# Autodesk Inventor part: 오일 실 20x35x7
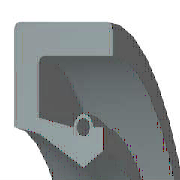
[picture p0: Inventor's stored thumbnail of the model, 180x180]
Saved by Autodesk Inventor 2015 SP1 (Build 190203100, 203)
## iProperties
IsCustomPart: 1
Created: 2012-02
Part Number: 오일 실 20x35x7
Material: 고무
Description: 회전 샤프트 립 유형 실 2 - 금속 케이스
Document SubType Name: Modeling
Standard: ISO 6194/1
Designer: mduedu
Standards Organization: ISO
Language: ko-KR
Size Designation: 20x35x7-유형 2
Categories: <MemberInstance><Categories><Category DisplayName="샤프트 부품" InternalName="7f7aeb1f-a693-4053-b835-cee3144e0d98" Mnemonic="SHFT"><Category DisplayName="실링" Intern
Density: 0.93 g/cm^3
Appearance: 고무 - 검은색 - 버전 1.1
Author: mduedu
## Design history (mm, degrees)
node "WorkPlane2"
node "WorkPoint1"
node "WorkPlane3"
body "Solid1"
node "스케치1"
revolve "회전1" stored, may be unused: angle "d37" = 360 deg
fillet "모깎기1" dims "d38" = 0.35 (= 0.05 x b)
sketch "스케치2"
  geometry: L1 (16, -0.35)-(16.8, -0.35); L2 (16, 0)-(16, -0.35); L3 (17.5, 0)-(16, 0); L4 (17.5, -7)-(17.5, 0); L5 (12.22, -7)-(17.5, -7); L6 (11.283, -4.2)-(12.22, -7); L7 (10.601, -3.72)-(11.283, -4.2); L8 (10, -1.925)-(10.601, -3.72); L9 (10.789, -1.05)-(10, -1.925); L10 (12.664, -1.05)-(10.789, -1.05); L11 (12.664, -1.925)-(12.664, -1.05); L12 (12.664, -5.6)-(12.664, -3.325); L13 (13.664, -5.6)-(12.664, -5.6); L14 (13.664, -6.3)-(13.664, -5.6); L15 (16.8, -6.3)-(13.664, -6.3); L16 (16.8, -0.35)-(16.8, -6.3); L17 (0, -15.959)-(0, 2.029); L18 (0, -15.959)-(0, 2.029); L19 (0, -19.557)-(0, 5.626) reference; L20 (-5.2, 0)-(31.2, 0) reference; A1 r 0.7 centre (12.664, -2.625) between (12.664, -3.325) and (12.664, -1.925)
  constraints: 36 end point, 7 vertical, 6 horizontal, 2 collinear, 2 point on circle, 1 centre point, 1 parallel, 1 point on line
  dimensions: "d2" = 0.35 distance of L2.start L1.start (= 0.05 x b); "d4" = 7 distance of L4.start L3.start (= b); "d6" = 0.7 horizontal distance of L1.end L3.start (= 0.1 x b); "d8" = 0.7 horizontal distance of L15.start L4.start (= 0.1 x b); "d10" = 0.7 distance of L14.start L13.start (= 0.1 x b); "d12" = 0.7 vertical distance of L1.end L10.start (= 0.1 x b); "d14" = 0.875 distance of L11.start L10.start (= 0.125 x b); "d16" = 0.7 radius of A1 (= 0.1 x b); "d18" = 0 horizontal distance of A1.centre L12.end; "d20" = 0.875 vertical distance of L9.start L8.start (= 0.125 x b); "d22" = 1.79487 vertical distance of L8.start L7.start (= 0.25641 x b); "d24" = 2.8 vertical distance of L6.start L5.start (= 0.4 x b); "d26" = 1.5 distance of L3.start L2.start (= 0.1 x dd - 0.1 x Diam); "d28" = 0.78947 horizontal distance of L9.start L8.start (= 0.0526316 x dd - 0.0526316 x Diam); "d30" = 1.875 distance of L10.start L9.start (= 0.125 x dd - 0.125 x Diam); "d32" = 1 distance of L13.start L12.start (= 0.0666667 x dd - 0.0666667 x Diam); "d34" = 0.9375 horizontal distance of L6.start L5.start (= 0.0625 x dd - 0.0625 x Diam); "d36" = 0.68182 horizontal distance of L7.start L6.start (= 0.0454545 x dd - 0.0454545 x Diam); "msp_d39" = 20 diameter of L8.start L17 (= Diam); "msp_d40" = 35 diameter of L4 L17 (= dd)
other parameters: "dd" = 35 [user parameter; used in 7 equation terms], "Diam" = 20 [user parameter; used in 7 equation terms], "b" = 7 [user parameter; used in 13 equation terms], "d0" = -7 (computed from b), "d1" = 0.4 (derived), "d3" = 8 (derived), "d5" = 0.8 (derived), "d7" = 0.8 (derived), "d9" = 0.8 (derived), "d11" = 0.8 (derived), "d13" = 1 (derived), "d15" = 0.8 (derived), "d17" = 0 (derived), "d19" = 1 (derived), "d21" = 2.05128 (derived), "d23" = 3.2 (derived), "d25" = 2 (derived), "d27" = 1.05263 (derived), "d29" = 2.5 (derived), "d31" = 1.33333 (derived), "d33" = 1.25 (derived), "d35" = 0.90909 (derived), "d42" = 0
